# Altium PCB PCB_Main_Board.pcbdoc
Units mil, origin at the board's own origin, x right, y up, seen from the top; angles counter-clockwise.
Board outline 4300.12 x 2475 mil, 2 copper layers (Top Layer, Bottom Layer), stack 2.757 mil thick; 10 components, 10 nets, 48 pads, 9 vias.
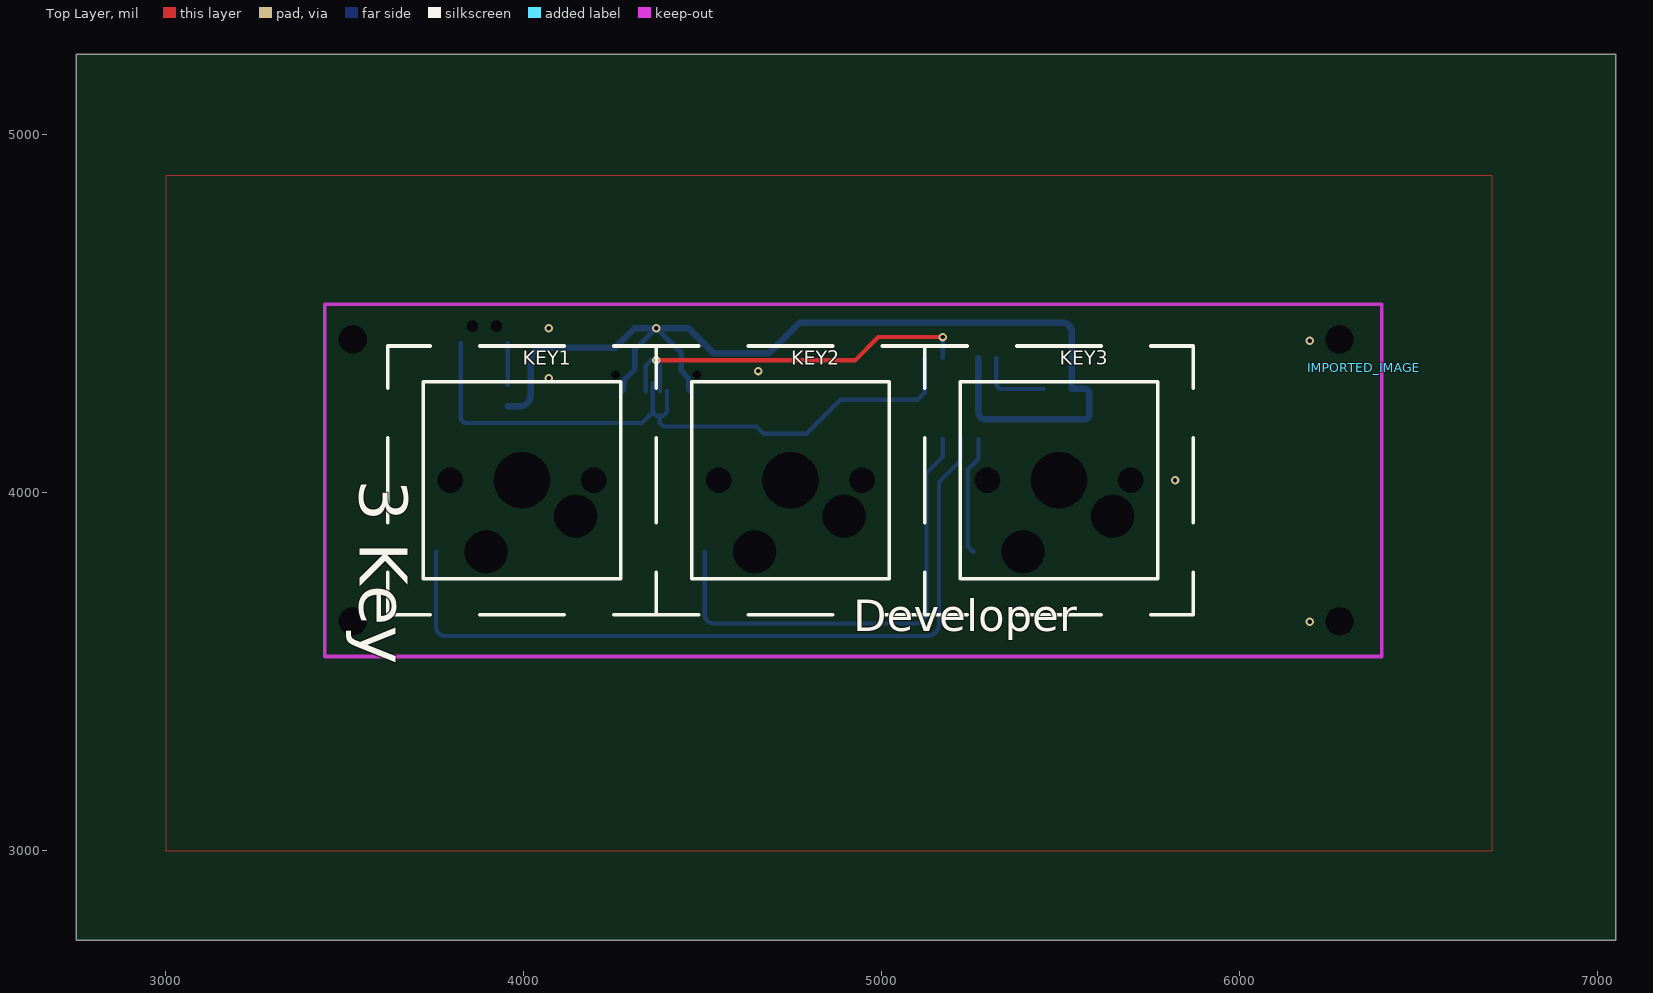
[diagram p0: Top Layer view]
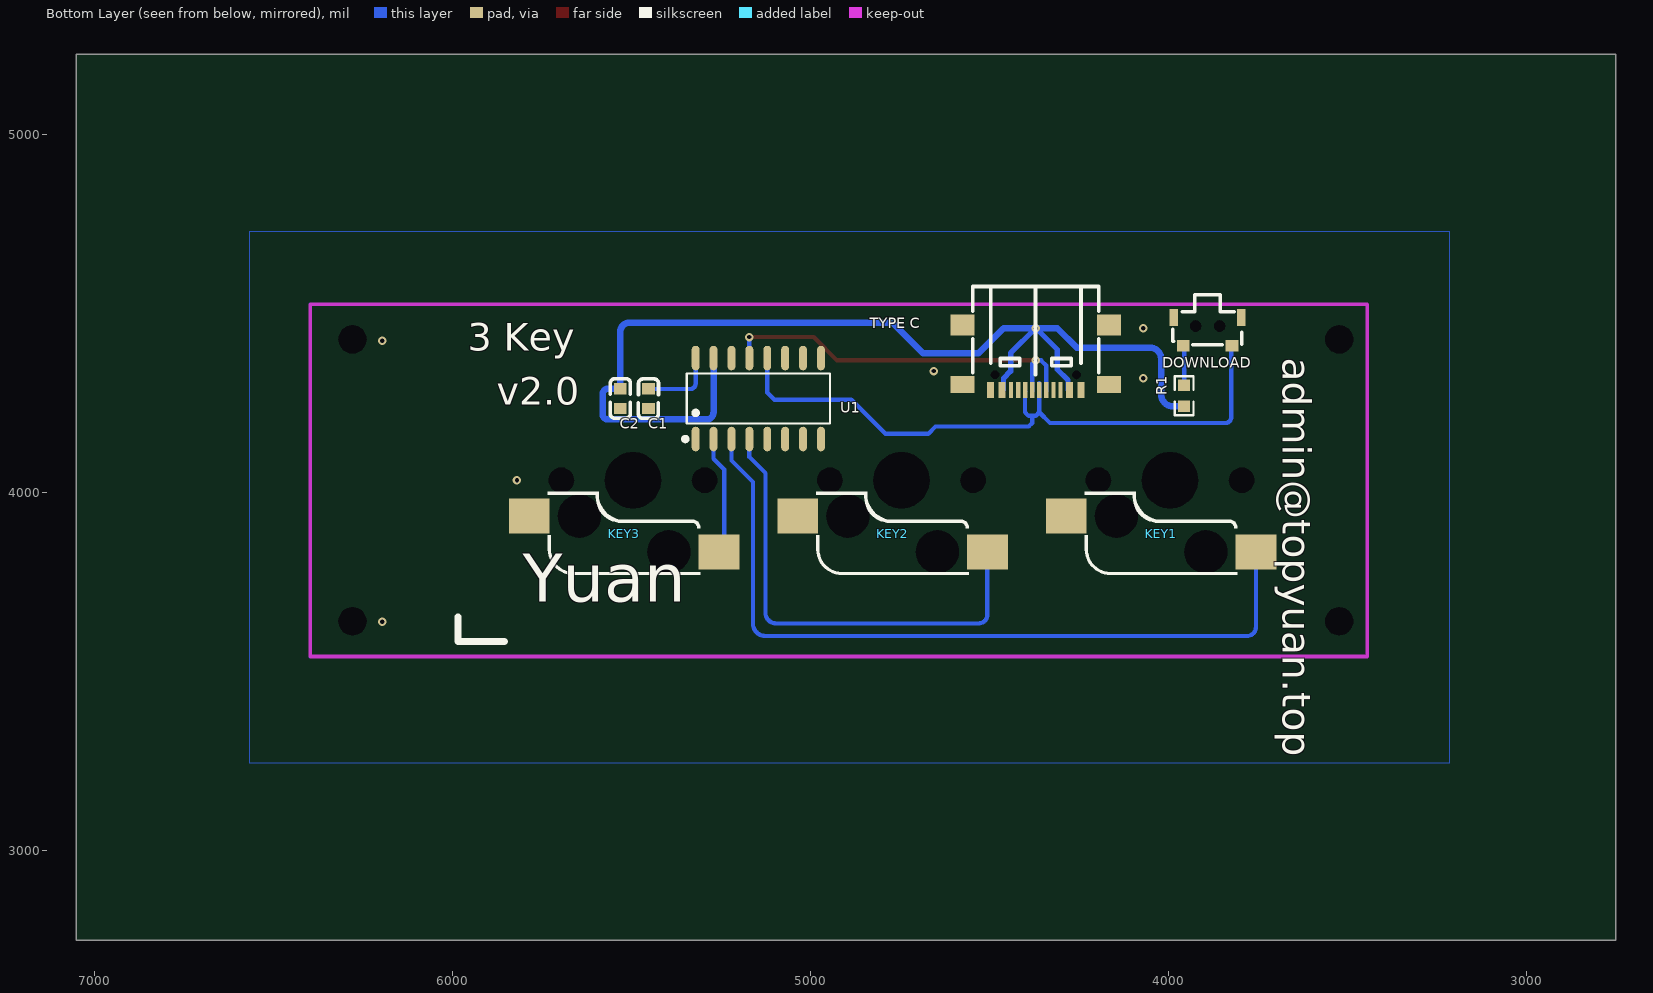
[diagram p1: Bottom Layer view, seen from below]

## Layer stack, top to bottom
Top Layer: signal copper 1.379
Bottom Layer: signal copper 1.378

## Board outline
7050.12,2750 2750,2750 2750,5225 7050.12,5225
cut-out: 6317.83,4428.7 ccw(c6278.46,4428.7) 6239.09,4428.7 ccw(c6278.46,4428.7)
cut-out: 6317.83,3641.3 ccw(c6278.46,3641.3) 6239.09,3641.3 ccw(c6278.46,3641.3)
cut-out: 3561.93,3641.3 ccw(c3522.56,3641.3) 3483.19,3641.3 ccw(c3522.56,3641.3)
cut-out: 3561.93,4428.7 ccw(c3522.56,4428.7) 3483.19,4428.7 ccw(c3522.56,4428.7)

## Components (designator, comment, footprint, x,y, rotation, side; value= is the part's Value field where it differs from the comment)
C1 "CC0603KRX7R9BB104" C0603 5451.69,4263.35 r90 bottom
C2 "CC0603KRX7R9BB104" C0603 5530.43,4263.35 r270 bottom
DOWNLOAD "TD-1100SA-250" SW-SMD_TD-1100SA-250 3890,4450 r180 bottom
IMPORTED_IMAGE "IMPORTED_IMAGE" IMPORTED_IMAGE 6348.19,4350 r0 top
KEY1 "五脚无灯热插拔轴体" 五脚无灯热插拔轴体 3995,4035 r0 top
KEY2 "五脚无灯热插拔轴体" 五脚无灯热插拔轴体 4745,4035 r0 top
KEY3 "五脚无灯热插拔轴体" 五脚无灯热插拔轴体 5495,4035 r0 top
R1 "0603WAF2002T5E" R0603 3955.63,4271.22 r270 bottom
"TYPE C" "TYPE-C 16P QTWT" USB-TYPE-C-SMD_TYPE-C-16P-QTWT 4370,4377.52 r0 bottom
U1 "CH552G" SOP-16_L10.0-W3.9-P1.27-LS6.0-BL 5145,4263.35 r180 bottom

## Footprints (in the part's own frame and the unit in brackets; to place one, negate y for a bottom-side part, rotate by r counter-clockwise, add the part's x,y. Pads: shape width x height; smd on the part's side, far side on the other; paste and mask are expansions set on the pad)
C0603 [mm]
  rect 0.8x0.9 smd: 1(-0.7,0) 2(0.7,0)
  silkscreen extent -1.41,-0.71 1.39,0.72
IMPORTED_IMAGE [mil]
R0603 [mil]
  rect 31.75x34.02 smd: 1(-29.66,0) 2(29.66,0)
  silkscreen extent -55,-26 55,26
SOP-16_L10.0-W3.9-P1.27-LS6.0-BL [mm]
  oval 0.56x1.745 smd: 1(-4.445,-2.872) 2(-3.175,-2.872) 3(-1.905,-2.872) 4(-0.635,-2.872) 5(0.635,-2.872) 6(1.905,-2.872) 7(3.175,-2.872) 8(4.445,-2.872) 9(4.445,2.872) 10(3.175,2.872) 11(1.905,2.872) 12(0.635,2.872) 13(-0.635,2.872) 14(-1.905,2.872) 15(-3.175,2.872) 16(-4.445,2.872)
  silkscreen extent -5.33,-3.02 5.08,1.77
SW-SMD_TD-1100SA-250 [mm]
  rect 0.9x0.8 smd: 1(-1.725,-1) 2(1.725,-1)
  rect 0.6x1.2 smd: 3(-2.4,1) 4(2.4,1)
  Multi-Layer board cut-out: -1.25,0.4 -1.211,0.574 -1.1,0.713 -0.939,0.79 -0.761,0.79 -0.601,0.713 -0.49,0.574 -0.45,0.4 -0.45,0.4 -0.49,0.226 -0.601,0.087 -0.761,0.01 -0.939,0.01 -1.1,0.087 -1.211,0.226 -1.25,0.4
  Multi-Layer board cut-out: 0.45,0.4 0.489,0.574 0.6,0.713 0.761,0.79 0.939,0.79 1.099,0.713 1.21,0.574 1.25,0.4 1.25,0.4 1.21,0.226 1.099,0.087 0.939,0.01 0.761,0.01 0.6,0.087 0.489,0.226 0.45,0.4
  silkscreen extent -2.47,-0.94 2.42,2.63
USB-TYPE-C-SMD_TYPE-C-16P-QTWT [mm]
  rect 1.7x1.5 smd: 0(-5.2,-2.309) 0(5.2,-2.309)
  rect 1.7x1.2 smd: 0(-5.2,1.891) 0(5.2,1.891)
  rect 0.5x1.14 smd: A1(-3.2,2.308) A4(-2.4,2.308) A9(2.4,2.308) A12(3.2,2.308)
  rect 0.3x1.14 smd: A5(-1.25,2.308) A6(-0.25,2.308) A7(0.25,2.308) A8(1.25,2.309) B5(1.75,2.308) B6(0.75,2.308) B7(-0.75,2.308) B8(-1.75,2.309)
  Multi-Layer board cut-out: 3.19,1.221 3.16,1.091 3.077,0.986 2.957,0.929 2.823,0.929 2.703,0.986 2.62,1.091 2.59,1.221 2.59,1.221 2.62,1.351 2.703,1.456 2.823,1.513 2.957,1.513 3.077,1.456 3.16,1.351 3.19,1.221
  Multi-Layer board cut-out: -2.59,1.221 -2.62,1.091 -2.703,0.986 -2.823,0.928 -2.957,0.928 -3.077,0.986 -3.16,1.091 -3.19,1.221 -3.19,1.221 -3.16,1.351 -3.077,1.455 -2.957,1.513 -2.823,1.513 -2.703,1.455 -2.62,1.351 -2.59,1.221
  silkscreen extent -4.46,-5.05 4.48,1.2
五脚无灯热插拔轴体 [mm]
  rect 2.9x2.5 smd far side: 1(-6.09,-5.08) 2(7.36,-2.54)
  Multi-Layer board cut-out: 1.995,0 1.797,0.866 1.244,1.56 0.444,1.945 -0.444,1.945 -1.244,1.56 -1.797,0.866 -1.995,0 -1.995,0 -1.797,-0.866 -1.244,-1.56 -0.444,-1.945 0.444,-1.945 1.244,-1.56 1.797,-0.866 1.995,0
  Multi-Layer board cut-out: -1.015,-5.08 -1.166,-4.418 -1.589,-3.888 -2.201,-3.593 -2.879,-3.593 -3.491,-3.888 -3.914,-4.418 -4.065,-5.08 -4.065,-5.08 -3.914,-5.742 -3.491,-6.272 -2.879,-6.567 -2.201,-6.567 -1.589,-6.272 -1.166,-5.742 -1.015,-5.08
  Multi-Layer board cut-out: 5.335,-2.54 5.184,-1.878 4.761,-1.348 4.149,-1.053 3.471,-1.053 2.859,-1.348 2.436,-1.878 2.285,-2.54 2.285,-2.54 2.436,-3.202 2.859,-3.732 3.471,-4.027 4.149,-4.027 4.761,-3.732 5.184,-3.202 5.335,-2.54
  Multi-Layer board cut-out: 5.98,0 5.891,0.39 5.641,0.704 5.28,0.877 4.88,0.877 4.519,0.704 4.269,0.39 4.18,0 4.18,0 4.269,-0.39 4.519,-0.704 4.88,-0.877 5.28,-0.877 5.641,-0.704 5.891,-0.39 5.98,0
  Multi-Layer board cut-out: -4.18,0 -4.269,0.39 -4.519,0.704 -4.88,0.877 -5.28,0.877 -5.641,0.704 -5.891,0.39 -5.98,0 -5.98,0 -5.891,-0.39 -5.641,-0.704 -5.28,-0.877 -4.88,-0.877 -4.519,-0.704 -4.269,-0.39 -4.18,0
  silkscreen extent -9.53,-9.53 9.53,9.53

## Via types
v1: diameter 24.02, hole 12.01, Top Layer to Bottom Layer, 9 vias

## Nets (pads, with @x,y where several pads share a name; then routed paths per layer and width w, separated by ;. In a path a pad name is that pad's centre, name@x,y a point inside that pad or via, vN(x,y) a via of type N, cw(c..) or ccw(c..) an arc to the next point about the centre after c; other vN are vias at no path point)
$1N453: C1.2 U1.16 | length 212.1
  Bottom Layer w12: U1.16 5320,4305 ccw(c5335,4305) 5335,4290 5450.79,4290 C1.2
$1N8802: DOWNLOAD.1 R1.1 | length 117.6
  Bottom Layer w12: R1.1 3955.63,4418.13 DOWNLOAD.1@3955.9,4418.4
DM: "TYPE C.A7" "TYPE C.B7" U1.13 | length 1083
  Top Layer w12: v1(4370,4370) 4925,4370 4990,4435 v1(5170,4435)
  Bottom Layer w12: 4340.48,4283.82 4340.48,4355.48 4355,4370 v1(4370,4370) 4379.85,4360.15 4379.85,4283.82 ; U1.13 v1(5170,4435)
DP: "TYPE C.A6" "TYPE C.B6" DOWNLOAD.2 U1.12 | length 1869.9
  Bottom Layer w12: DOWNLOAD.2@3824.1,4418.4 3824.1,4210.9 ccw(c3840,4210.9) 3840,4195 4330.33,4195 4360.16,4224.84 ; 4360.16,4305.99 4360.16,4224.84 ; 4399.53,4283.82 4400,4283.35 4400,4225 4390,4215 4379.63,4215 ; U1.12 5120,4280 5100,4260 4885,4260 4790,4165 4670,4165 4650,4185 4390,4185 4380,4195 4380,4214.63 4379.63,4215 ; 4360.16,4224.84 4370,4215 4379.63,4215
GND: "TYPE C.0" "TYPE C.A1" "TYPE C.A12" C1.1 C2.2 DOWNLOAD.3 DOWNLOAD.4 KEY1.2 KEY2.2 KEY3.2 U1.14
  other v1: 6195,3640 5819.21,4035 4070,4320 4655,4340 6195,4425 4070,4460
SW1: KEY1.1 U1.3 | length 2189.5
  Bottom Layer w12: KEY1.1 3755,3834.76 3755,3625 ccw(c3780,3625) 3780,3600 5125,3600 ccw(c5125,3635) 5160,3635 5160,4030 5220,4090 U1.3
SW2: KEY2.1 U1.4 | length 1330.2
  Bottom Layer w12: KEY2.1 4505.24,3659.76 ccw(c4530,3659.76) 4530,3635 5095,3635 ccw(c5095,3665) 5125,3665 5125,4055 5170,4100 U1.4
SW3: KEY3.1 U1.2 | length 334
  Bottom Layer w12: KEY3.1 5240,3850.24 5240,4065 5270,4095 U1.2
VCC: "TYPE C.A4" "TYPE C.A9" C2.1 R1.2 U1.15 | length 2997.1
  Bottom Layer w15: 4275.52,4283.82 4280,4288.3 4280,4315 4310,4345 4310,4400 v1(4370,4460) 4440,4390 4440,4339.78 4460,4319.78 4460,4288.31 4464.49,4283.82
  Bottom Layer w18: R1.2 3986.56,4241.56 ccw(c3986.56,4275) 4020,4275 4020,4375 cw(c4050,4375) 4050,4405 4255,4405 4310,4460 v1(4370,4460) 4460,4460 4530,4390 4685,4390 4770,4475 5505.45,4475 cw(c5505.45,4450.02) 5530.43,4450.02 C2.1 5564.09,4290.91 cw(c5564.09,4275) 5580,4275 5580,4220 cw(c5565,4220) 5565,4205 5290,4205 cw(c5290,4225) 5270,4225 U1.15
"": "TYPE C.A5" "TYPE C.A8" "TYPE C.B5" "TYPE C.B8" U1.1 U1.5 U1.6 U1.7 U1.8 U1.9 U1.10 U1.11

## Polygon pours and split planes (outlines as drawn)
GND on Bottom Layer (solid, remove dead copper, pour order 0): 3215,3245 6565,3245 6565,4730 3215,4730
GND on Top Layer (solid, remove dead copper, pour order 1): 3000,3000 6705,3000 6705,4885 3000,4885

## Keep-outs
Keep-Out Layer:
  lines w10 net "": 3443.82,3542.87 6396.57,3542.87 6396.57,4527.13 3443.82,4527.13 3443.82,3542.87

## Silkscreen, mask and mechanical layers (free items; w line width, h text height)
Top Silkscreen Layer:
  text "3 Key" at 3542.5,4035.85 h133.8 r270
  text "Developer" at 4919.63,3613.55 h89.2
Bottom Silkscreen Layer:
  lines w19 net "": 5854.09,3585 5984.02,3585 5984.02,3653.9
  text "3 Key" at 5956.51,4396.64 h77.88
  text "admin@topyuan.top" at 3679.63,4377.15 h79.3 r90
  text "v2.0" at 5874.93,4246.64 h77.88
  text "Yuan" at 5802.38,3696.08 h133.8
Mechanical 1:
  circle w1 net "": c6278.46,4428.7 r39.37
  circle w1 net "": c6278.46,3641.3 r39.37
  circle w1 net "": c3522.56,3641.3 r39.37
  circle w1 net "": c3522.56,4428.7 r39.37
